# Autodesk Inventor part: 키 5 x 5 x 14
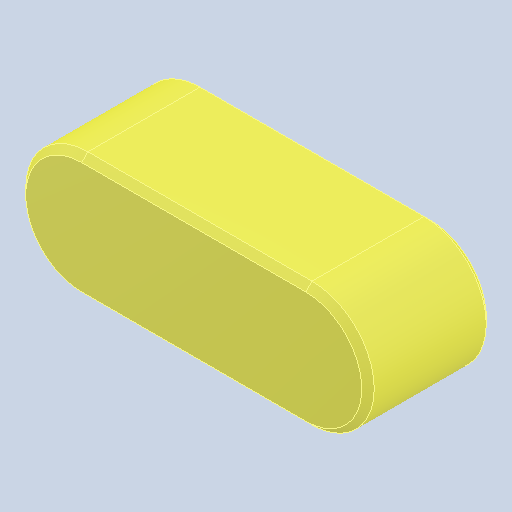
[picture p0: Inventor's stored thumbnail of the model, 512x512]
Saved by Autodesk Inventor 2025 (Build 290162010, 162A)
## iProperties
Created: 2024-07
Part Number: 키 5 x 5 x 14
Material: 강철, 연강
Description: 키 및 해당 키홈
Document SubType Name: Modeling
Designer: Admin
Density: 7.85 g/cm^3
Appearance: 기본값
Author: jhkim
Sending System: Autodesk Inventor 2025
Preprocessor: ST-DEVELOPER v20
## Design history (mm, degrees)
feature "Solid1"
node "솔리드1"
